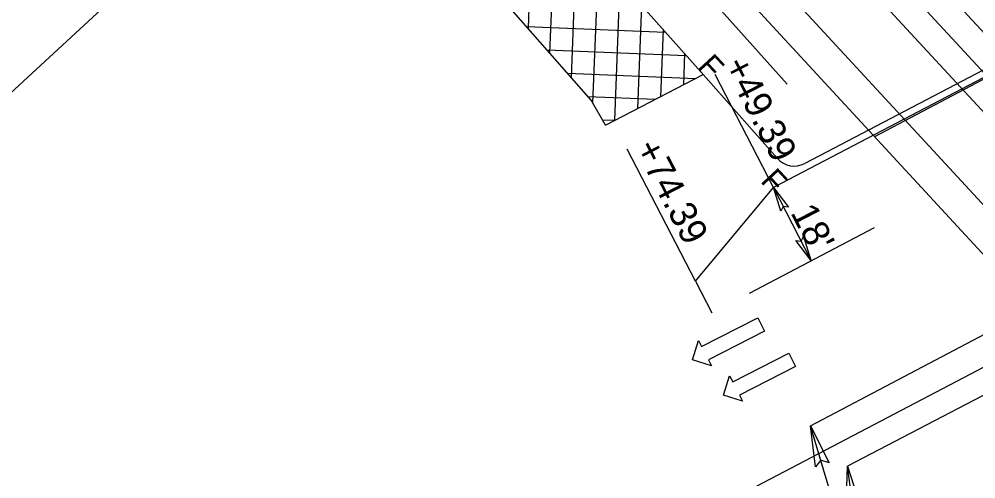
# Model space of a CAD drawing. Extents: x 1702862 to 1704514, y 793768 to 796215.
# Drawn here: x 1703316.6 to 1703529.1, y 794921.9 to 795023.9 of the extents above; entities that cross this region are included whole.
import ezdxf

# ---------------------------------------------------------------- set-up
doc = ezdxf.new("R2010")
doc.units = 0
for name, color, linetype in [('Exist Horizontal Alignment', 7, 'Continuous'), ('Old_Level_30', 7, 'Continuous'), ('Prop Dimension', 7, 'Continuous'), ('Prop Dimension Text', 7, 'Continuous'), ('Prop EOT', 7, 'Continuous'), ('Prop Guardrail', 7, 'Continuous'), ('Prop Horizontal Alignment', 7, 'Continuous'), ('Prop Lane Arrow CELL', 7, 'Continuous'), ('Prop Lane Lines', 7, 'Continuous'), ('Prop Leader Line Medium', 7, 'Continuous'), ('Prop Rem of Exist Asph Pvmt', 7, 'Continuous'), ('Prop Roadway Bridge', 7, 'Continuous'), ('Prop SS Fill Line', 7, 'Continuous'), ('Prop SS Misc', 7, 'Continuous'), ('Prop Terminator CELL', 7, 'Continuous')]:
    doc.layers.add(name, color=color, linetype=linetype)

msp = doc.modelspace()

# ---------------------------------------------------------------- linework, layer by layer
at = {"layer": 'Exist Horizontal Alignment'}
msp.add_line((1703731.56, 795051.6), (1703391.21, 794873.6), dxfattribs=at)
at = {"layer": 'Old_Level_30'}
msp.add_line((1703487.22, 795009.46), (1703461.25, 795038.56), dxfattribs=at)
at = {"layer": 'Prop Dimension'}
msp.add_line((1703272.02, 794968.13), (1703418.98, 795103.79), dxfattribs=at)
msp.add_arc((1703324.13, 795065.01), 90, 136.7565, 136.7565, dxfattribs=at)
at = {"layer": 'Prop Dimension Text'}
for p, q in [((1703484.16, 794986.54), (1703471.2, 795011.62)), ((1703466.82, 794965.73), (1703451.69, 794995.02)), ((1703484.16, 794986.54), (1703492.48, 794970.42)), ((1703478.81, 794963.05), (1703506.62, 794977.63))]:
    msp.add_line(p, q, dxfattribs=at)
at = {"layer": 'Prop EOT'}
for p, q in [((1703418.98, 795103.79), (1703636.58, 794868.05)), ((1703573.9, 795033.47), (1703484.16, 794986.54)), ((1703466.82, 794965.73), (1703484.16, 794986.54)), ((1703466.82, 794965.73), (1703470.49, 794958.71))]:
    msp.add_line(p, q, dxfattribs=at)
msp.add_lwpolyline([(1703551.93, 795021.68), (1703506.62, 794997.79)], dxfattribs=at)
at = {"layer": 'Prop Guardrail'}
for p, q in [((1703492.38, 794933.6), (1703566.95, 794972.97)), ((1703575.44, 794963.77), (1703500.62, 794924.67))]:
    msp.add_line(p, q, dxfattribs=at)
at = {"layer": 'Prop Horizontal Alignment'}
msp.add_line((1703246.67, 795319.94), (1703723.92, 794802.92), dxfattribs=at)
at = {"layer": 'Prop Lane Arrow CELL'}
for p, q in [((1703468.2, 794951.23), (1703480.67, 794957.59)), ((1703480.67, 794957.59), (1703482.17, 794954.65)), ((1703482.17, 794954.65), (1703469.7, 794948.29)), ((1703466.17, 794948.28), (1703467.52, 794952.56)), ((1703467.52, 794952.56), (1703468.2, 794951.23)), ((1703475.1, 794943.39), (1703487.57, 794949.76)), ((1703487.57, 794949.76), (1703489.07, 794946.82)), ((1703470.39, 794946.95), (1703466.17, 794948.28)), ((1703469.7, 794948.29), (1703470.39, 794946.95)), ((1703489.07, 794946.82), (1703476.61, 794940.45)), ((1703473.07, 794940.45), (1703474.42, 794944.73)), ((1703474.42, 794944.73), (1703475.1, 794943.39)), ((1703477.29, 794939.12), (1703473.07, 794940.45)), ((1703476.61, 794940.45), (1703477.29, 794939.12))]:
    msp.add_line(p, q, dxfattribs=at)
at = {"layer": 'Prop Lane Lines'}
for p, q in [((1703347.89, 795219.14), (1703550.56, 794999.58)), ((1703339.07, 795211), (1703542.22, 794990.92))]:
    msp.add_line(p, q, dxfattribs=at)
at = {"layer": 'Prop Leader Line Medium'}
for q in [(1703492.38, 794933.6), (1703500.62, 794924.67)]:
    msp.add_line((1703505.35, 794890.4), q, dxfattribs=at)
at = {"layer": 'Prop Rem of Exist Asph Pvmt'}
for p, q in [((1703430.85, 795052.52), (1703429.63, 795021.89)), ((1703435.69, 795048.47), (1703434.41, 795016.44)), ((1703440.48, 795043.1), (1703439.2, 795010.99)), ((1703445.27, 795037.73), (1703443.98, 795005.35)), ((1703450.06, 795032.37), (1703448.82, 795001.4)), ((1703454.85, 795027), (1703453.93, 795004.05)), ((1703429.29, 795022.28), (1703460.16, 795021.04)), ((1703459.64, 795021.63), (1703459.04, 795006.69)), ((1703433.84, 795017.09), (1703464.79, 795015.85)), ((1703464.43, 795016.26), (1703464.15, 795009.34)), ((1703438.39, 795011.91), (1703466.9, 795010.77)), ((1703446.88, 795000.39), (1703468.56, 795011.63)), ((1703446.88, 795000.39), (1703468.56, 795011.63)), ((1703442.94, 795006.72), (1703457.94, 795006.12)), ((1703446.18, 795001.59), (1703448.97, 795001.48))]:
    msp.add_line(p, q, dxfattribs=at)
msp.add_lwpolyline([(1703446.88, 795000.39), (1703443.63, 795005.93), (1703413.93, 795039.78), (1703381.07, 795076.19), (1703353.81, 795105.47)], dxfattribs=at)
at = {"layer": 'Prop Roadway Bridge'}
msp.add_line((1703480.41, 795026.18), (1703613.32, 794882.19), dxfattribs=at)
at = {"layer": 'Prop SS Fill Line'}
for p, q in [((1703434.77, 795049.5), (1703468.06, 795012.19)), ((1703578.45, 795037.54), (1703491.11, 794991.87)), ((1703468.06, 795012.19), (1703485.05, 794992.98))]:
    msp.add_line(p, q, dxfattribs=at)
msp.add_arc((1703488.8, 794996.3), 5, 221.4926, 297.6095, dxfattribs=at)
at = {"layer": 'Prop Terminator CELL'}
for points in [[(1703485.81, 794981.31), (1703484.16, 794986.54), (1703487.5, 794982.15), (1703486.33, 794982.32)], [(1703490.83, 794975.64), (1703492.48, 794970.42), (1703489.14, 794974.8), (1703490.31, 794974.63)], [(1703493.48, 794924.54), (1703492.38, 794933.6), (1703496.51, 794925.4), (1703494.65, 794926.04)], [(1703500.32, 794915.54), (1703500.62, 794924.67), (1703503.45, 794915.92), (1703501.7, 794916.85)]]:
    msp.add_lwpolyline(points, close=True, dxfattribs=at)

# ---------------------------------------------------------------- texts
at = {"layer": 'Prop Dimension Text'}
for s, p in [('+49.39', (1703472.96, 795013.69)), ('+74.39', (1703453.25, 794995.35)), ("18'", (1703487.86, 794980.98))]:
    msp.add_text(s, height=6, rotation=297.3125, dxfattribs=at).set_placement(p)
at = {"layer": 'Prop SS Misc'}
for p in [(1703467.1, 795013.23), (1703481.09, 794987.86)]:
    msp.add_text('F', height=5, rotation=312.7091, dxfattribs=at).set_placement(p)

doc.saveas('drawing.dxf')
